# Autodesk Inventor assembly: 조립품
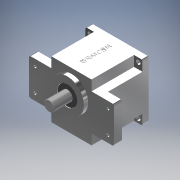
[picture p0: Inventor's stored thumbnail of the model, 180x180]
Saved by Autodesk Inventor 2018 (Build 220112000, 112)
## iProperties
Created: 2020-07
Part Number: 조립품
Material: 일반
Document SubType Name: Assembly
Designer: Admin
Author: Admin
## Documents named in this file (10)
- C:\Users\Admin\Desktop\700707V1001\조립품.iam
- C:\Users\Admin\Desktop\700707V1001\본체.ipt
- C:\Users\Admin\Desktop\700707V1001\커버.ipt
- C:\Users\Admin\Desktop\700707V1001\서브 축.ipt
- C:\Users\Admin\Desktop\700707V1001\메인 축.ipt
- C:\Users\Admin\Desktop\700707V1001\베어링 608.ipt
- C:\Users\Admin\Desktop\700707V1001\베어링 6003.ipt
- C:\Users\Admin\Desktop\700707V1001\오일 실 8 22 7.ipt
- C:\Users\Admin\Desktop\700707V1001\오일 실 17 32 8.ipt
- C:\Users\Admin\Desktop\700707V1001\볼트 M4.ipt
